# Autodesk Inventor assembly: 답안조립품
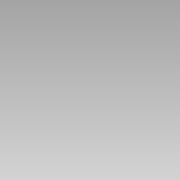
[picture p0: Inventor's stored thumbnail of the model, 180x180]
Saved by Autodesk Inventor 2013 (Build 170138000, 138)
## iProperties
Created: 2019-04
Part Number: 답안조립품
Document SubType Name: Assembly
Designer: Administrator
Author: Administrator
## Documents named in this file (1)
- C:\Users\Administrator\Desktop\490407v1031\답안조립품.iam
